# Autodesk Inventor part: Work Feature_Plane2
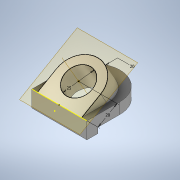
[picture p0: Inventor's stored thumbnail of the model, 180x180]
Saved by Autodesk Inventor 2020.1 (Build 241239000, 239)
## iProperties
Created: 2019-10
Part Number: Work Feature_Plane2
Material: Silicon Nitride
Document SubType Name: Modeling
Designer: Synergysoft Dell02
Density: 3.18 g/cm^3
Appearance: Chrome - Polished Black
Author: Synergysoft Dell02
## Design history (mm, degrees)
sketch "Sketch1"
  geometry: L1 (25, 0)-(25, -30); L2 (-25, -30)-(-25, 0); L3 (-25, 0)-(25, 0); L4 (25, 0)-(-25, 0); L5 (-25, 0)-(-25, -10); L6 (-25, -10)-(25, -10); L7 (25, -10)-(25, 0); A1 r 25 centre (0, -30) between (-25, -30) and (25, -30); 3 further points
  constraints: 14 end point, 3 parallel, 2 perpendicular, 2 point on circle, 2 tangent, 1 centre point, 1 coincident, 1 horizontal, 1 midpoint, 1 point on line, 1 vertical
  dimensions: "d0" = 50 distance of L2.end L1.start; "d1" = 30 distance from line of L3 A1.centre; "d2" = 10 distance between parallel lines of L3 L6
extrude "Extrusion1" new body sketch "Sketch1" distance "d3" = 10; taper "d4" = 0 deg
extrude "Extrusion2" join sketch "Sketch1" distance "d5" = 5; taper "d6" = 0 deg
workplane "Work Plane1"
sketch "Sketch2"
  geometry: L1 (0, 0)-(50, 0) reference; L2 (5, 0)-(5, 20); L3 (45, 20)-(45, 0); A1 r 20 centre (25, 20) between (45, 20) and (5, 20); 1 further point
  constraints: 4 end point, 2 point on circle, 2 point on line, 2 tangent, 1 centre point, 1 midpoint, 1 parallel, 1 perpendicular, 1 vertical alignment
  dimensions: "d15" = 20 radius of A1; "d16" = 20 distance from line of L1 A1.centre
extrude "Extrusion3" join sketch "Sketch2" stored distance "d10" = 10; taper "d11" = 0 deg
sketch "Sketch3"
  geometry: C1 r 12.5 at (25, 20); A1 r 20 centre (25, 20) between (45, 20) and (5, 20) reference; 1 further point
  constraints: 1 centre point, 1 concentric
  dimensions: "d17" = 25 diameter of C1
extrude "Extrusion4" cut sketch "Sketch3" distance "d18" = 47.25; taper "d19" = 0 deg
workaxis "Work Axis1"
workpoint "Work Point1"
body "Solid1"
other parameters: "d7" = -60 deg
